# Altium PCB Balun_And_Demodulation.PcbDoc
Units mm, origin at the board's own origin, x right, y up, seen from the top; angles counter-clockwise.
Board outline 152.4 x 101.6 mm, 4 copper layers (Top Layer, GND, VCC, Bottom Layer), stack 1.593 mm thick; 57 components, 41 nets, 285 pads, 244 vias.
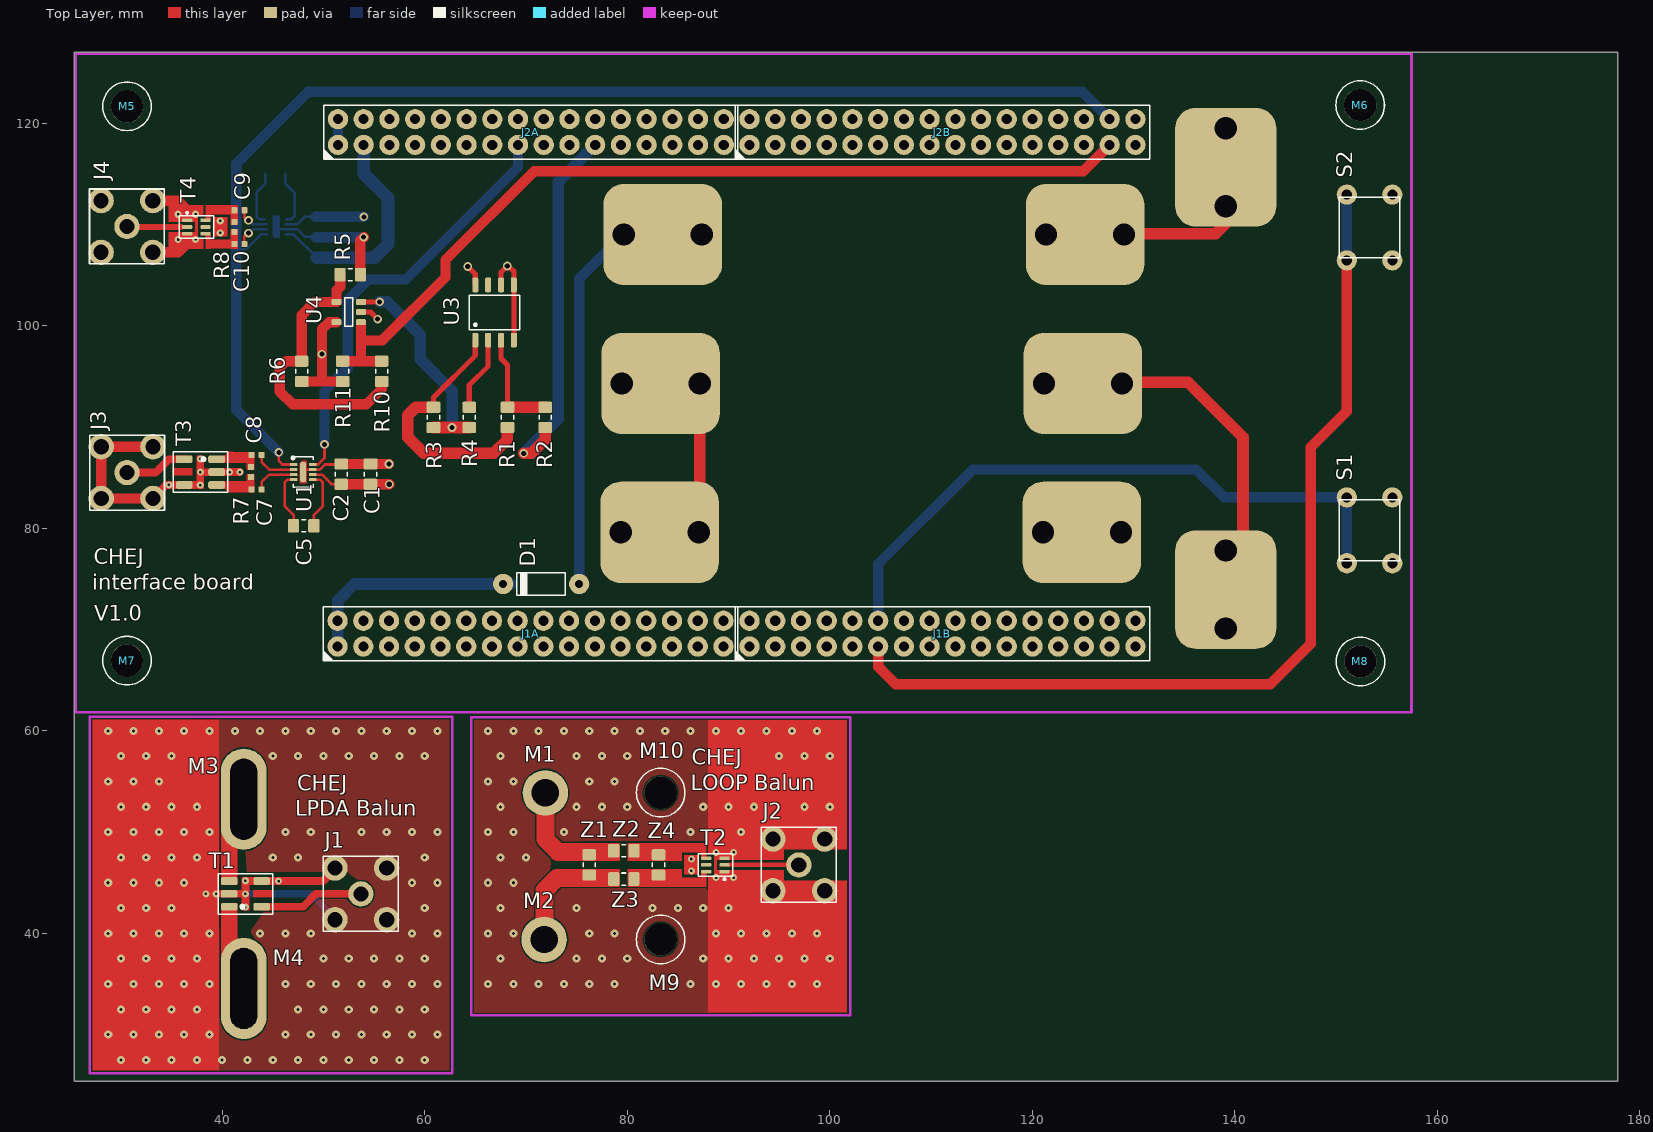
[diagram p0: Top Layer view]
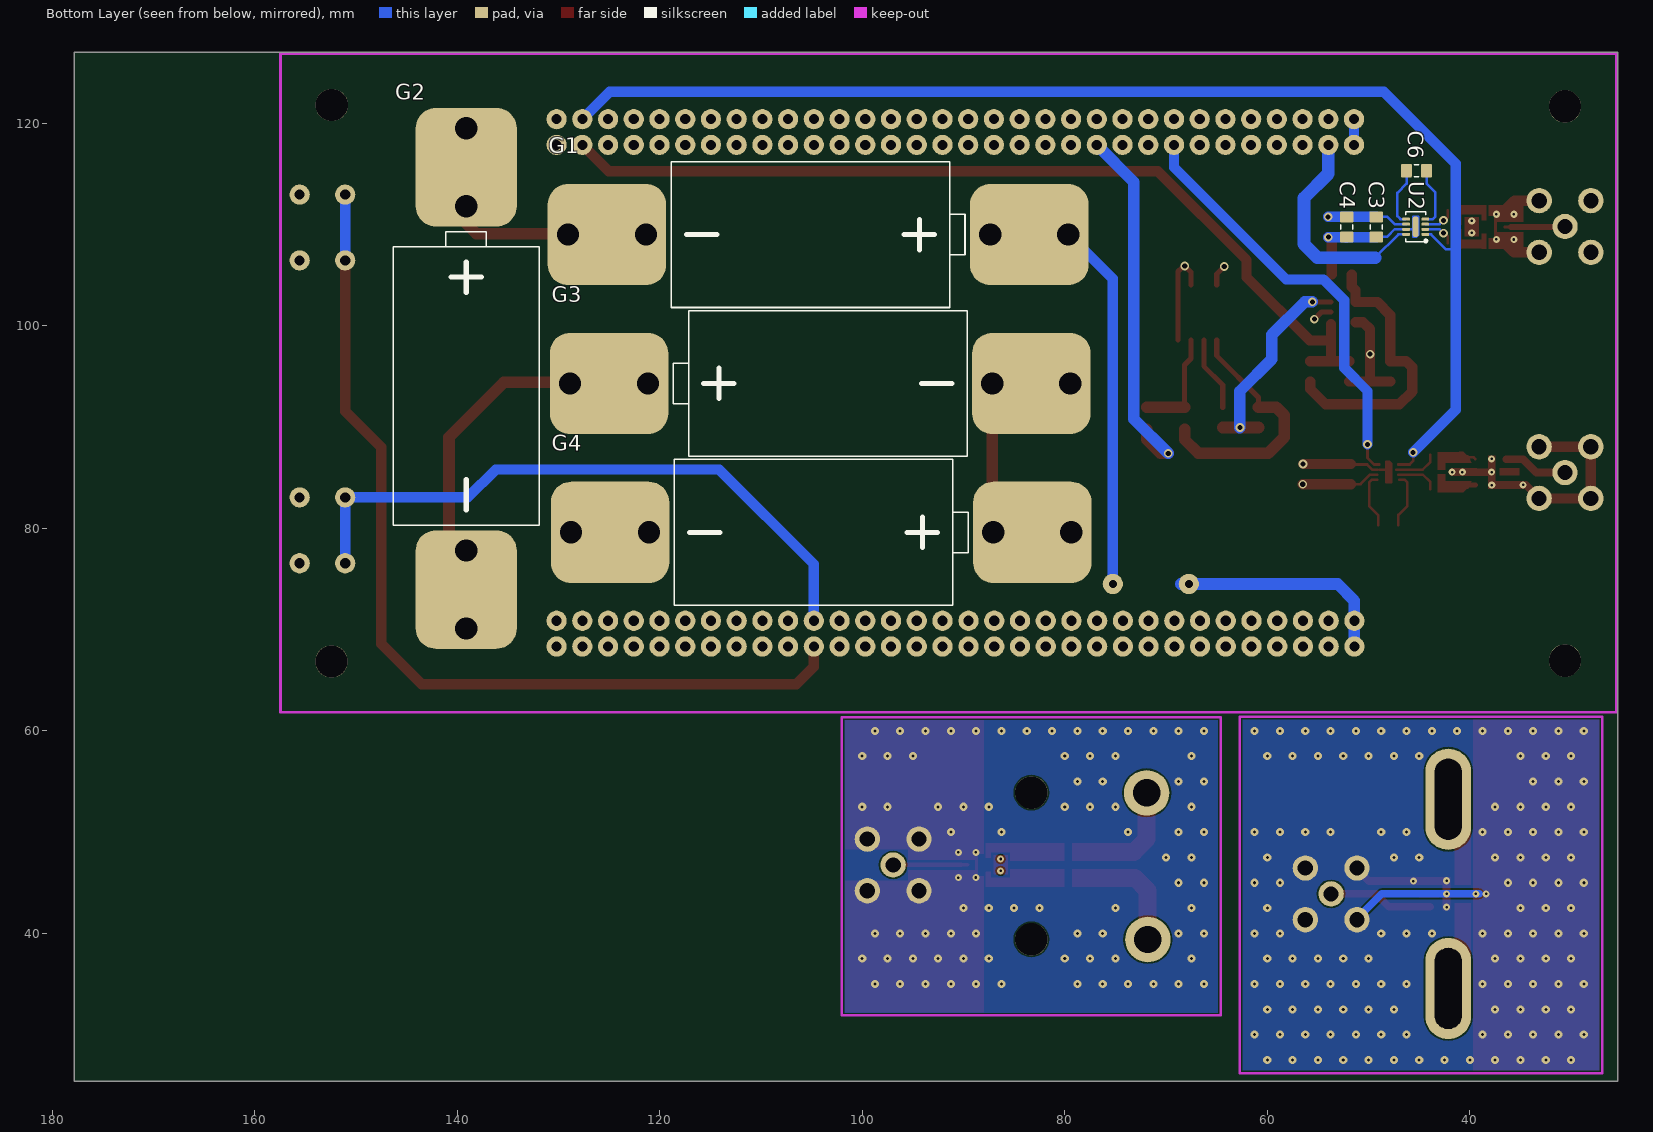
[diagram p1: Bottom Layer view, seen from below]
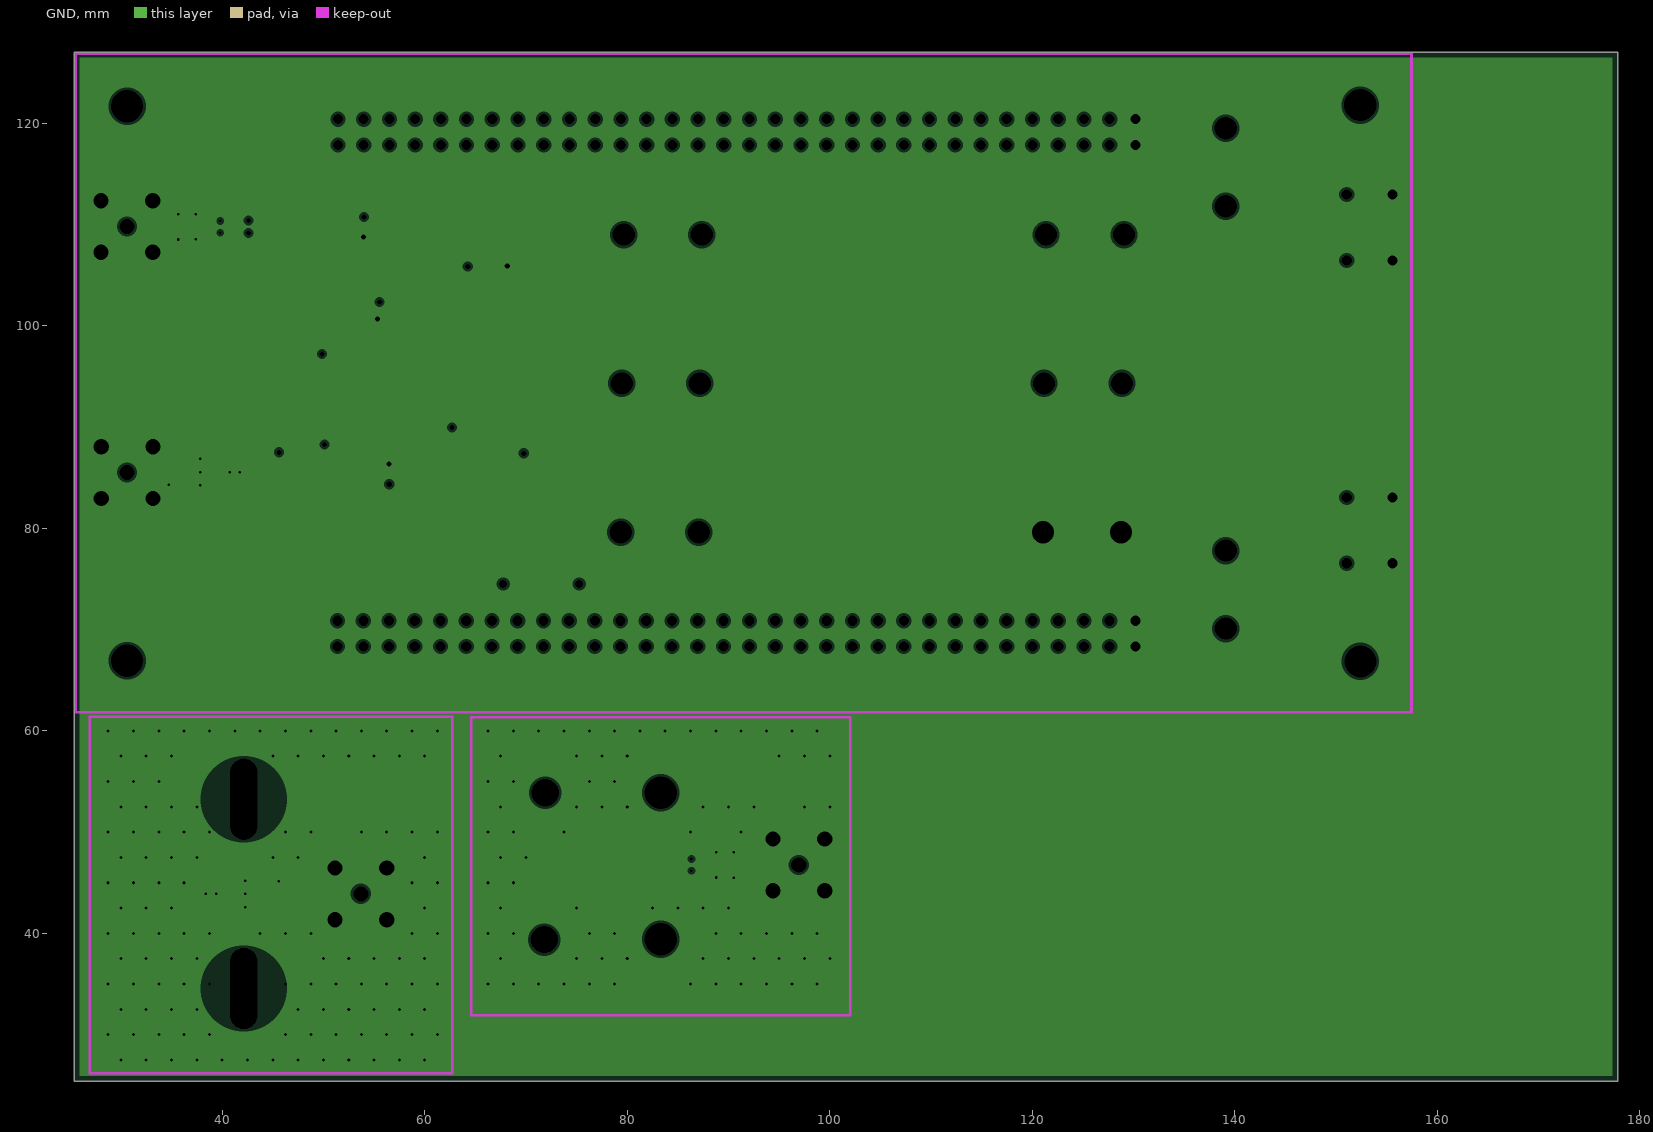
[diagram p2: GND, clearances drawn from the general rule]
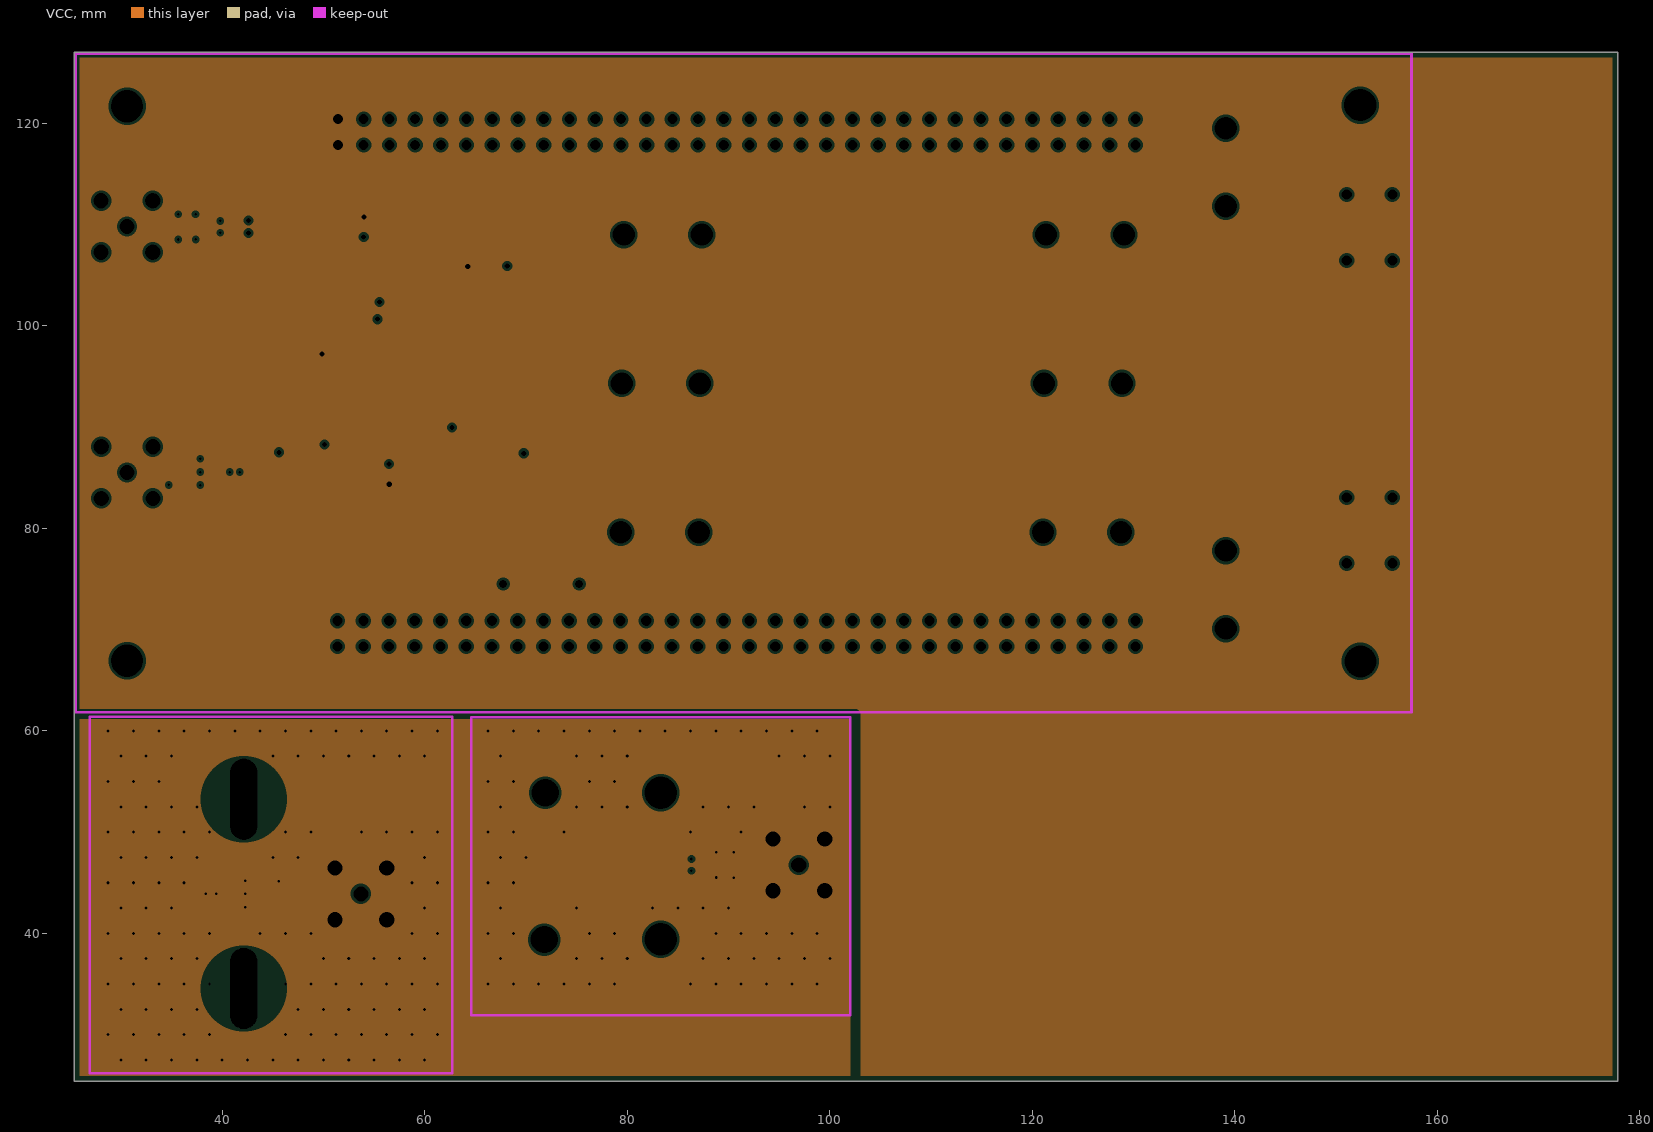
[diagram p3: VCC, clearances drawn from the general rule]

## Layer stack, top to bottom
Top Solder: solder mask 0.0102, Solder Resist, Dk 3.5
Top Layer: signal copper 0.0356
Dielectric 1: core 0.36, FR-4, Dk 4.2
GND: plane copper 0.036, net GND
Dielectric 5: prepreg 0.73, Dk 4.2
VCC: plane copper 0.036, net (Multiple Nets)
Dielectric 3: core 0.36, Dk 4.2
Bottom Layer: signal copper 0.0356
Bottom Solder: solder mask 0.0102, Solder Resist, Dk 3.5

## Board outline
25.4,25.4 177.8,25.4 177.8,127 25.4,127

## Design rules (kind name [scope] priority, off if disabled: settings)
BoardOutlineClearance [All] p1: gap=0.25 ignorepadtopadclearanceinfootprint=FALSE except(0: Arc-SplitContinuation Track-SplitContinuation SMDPad-SplitContinuation THPad-SplitContinuation Via-SplitContinuation Fill-SplitContinuation Poly-SplitContinuation Region-SplitContinuation Text-SplitContinuation)
Clearance Clearance-xPP-xTP-xTT [All] p1: gap=0.15 ignorepadtopadclearanceinfootprint=FALSE except(0: Arc-Hole Track-Hole SMDPad-Hole THPad-Hole Via-Hole Fill-Hole Poly-Hole Region-Hole Text-Hole)
ComponentClearance [All] p1: gap=0.25 collisioncheckmode=3 verticalgap=0.25 showdistances=FALSE
DiffPairsRouting [All] p1: maxlimit=0.25 minlimit=0.25 mostfreqgap=0.25 toplayer_minwidth=0.381 toplayer_maxwidth=0.381 toplayer_prefwidth=0.381 bottomlayer_minwidth=0.381 bottomlayer_maxwidth=0.381 bottomlayer_prefwidth=0.381 maxuncoupledlength=12.5
Height [All] p1: minheight=0 maxheight=25 prefheight=12.5
HoleSize HoleSize-PTH [All] p1: absolutevalues=TRUE maxlimit=2 minlimit=0.25 maxpercent=80.000 minpercent=20.000
HoleToHoleClearance [All] p1: gap=0.35 allowstackedmicrovias=TRUE
MinimumAnnularRing "Minimum IAR  >0.45mm" [((ObjectKind = 'Pad') OR (ObjectKind = 'Via')) And (Layer = 'MultiLayer') And (HoleDiameter > AsMM(0.45))] p1: minimumring=0.175 // minimum inner annular ring for pads > 0.45mm finished hole size
MinimumAnnularRing "Minimum IAR <=0.45mm" [((ObjectKind = 'Pad') OR (ObjectKind = 'Via')) And (Layer = 'MultiLayer') And (HoleDiameter <= AsMM(0.45))] p2: minimumring=0.175 // minimum inner annular ring for pads <= 0.45mm finished hole size
MinimumSolderMaskSliver [All] p1: minsoldermaskwidth=0.08
PlaneClearance PlaneClearance-IPI [All] p1: clearance=0.254
PlaneConnect [All] p1: planeconnectstyle=Direct reliefexpansion=0.175 reliefentries=4 reliefconductorwidth=0.2 reliefairgap=0.2
PolygonConnect PolygonConnect-xTW [All] p1: connectstyle=Direct reliefconductorwidth=0.2 reliefentries=4 polygonreliefangle="90 Angle" airgapwidth=0.2
RoutingCorners [All] p1: cornerstyle=45-Degree minsetback=2.5 maxsetback=2.5
RoutingVias "RoutingVias > 0.45mm" [(ObjectKind = 'Via') And (HoleDiameter > AsMM(0.45))] p1: holewidth=0.5 width=0.85 viastyle="Through Hole" minholewidth=0.5 minwidth=0.85 maxholewidth=0.9 maxwidth=1.25 // finishet hole size > 0.45mm
RoutingVias "RoutingVias <= 0.45mm" [(ObjectKind = 'Via') And (HoleDiameter <= AsMM(0.45))] p2: holewidth=0.3 width=0.65 viastyle="Through Hole" minholewidth=0.25 minwidth=0.6 maxholewidth=0.45 maxwidth=0.8 // finishet hole size <= 0.45mm
SilkToSilkClearance [All] p1: silktosilkclearance=0.2
SilkToSolderMaskClearance SilkscreenOverComponentPads [IsPad] p1: minsilkscreentomaskgap=0.2 clearancetoexposedcopper=TRUE
SolderMaskExpansion [All] p1: expansion=0
UnRoutedNet [All] p1: checkbadconnections=TRUE
Width Width-xTW [All] p1 off: maxlimit=1.5 minlimit=0.15 preferedwidth=0.2
18 further rules are at their usual default settings.

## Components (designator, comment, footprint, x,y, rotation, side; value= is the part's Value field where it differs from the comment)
C1 "1nF" "CAPACITOR 2012 REFLOW" 54.65,85.35 r270 top
C2 "100nF" "CAPACITOR 2012 REFLOW" 51.75,85.35 r270 top
C3 "100nF" "CAPACITOR 2012 REFLOW" 49.25,109.75 r90 bottom
C4 "1nF" "CAPACITOR 2012 REFLOW" 52.15,109.75 r90 bottom
C5 "*" "CAPACITOR 2012 REFLOW" 48.05,80.25 r180 top
C6 "*" "CAPACITOR 2012 REFLOW" 45.27,115.308 r180 bottom
C7 "=Value" "CAPACITOR 1005 REFLOW" 43.399,83.85 r180 top
C8 "=Value" "CAPACITOR 1005 REFLOW" 43.4,87.25 r180 top
C9 "=Value" "CAPACITOR 1005 REFLOW" 41.699,111.4 r180 top
C10 "=Value" "CAPACITOR 1005 REFLOW" 41.699,108.05 r180 top
D1 "*" "DIODE DO35 P7.5" 71.5,74.5 r0 top
G1 "1.5V" "1.5V Cell AA/LR6" 104.35,109 r0 bottom
G2 "1.5V" "1.5V Cell AA/LR6" 139.1,94.8 r270 bottom
G3 "1.5V" "1.5V Cell AA/LR6" 104.15,94.3 r180 bottom
G4 "1.5V" "1.5V Cell AA/LR6" 104.05,79.6 r0 bottom
J1 "CONSMA001-G" "SMA TH Vertical Linx CONSMA001-G" 53.696,43.9 r0 top
J1A "*" "PinHeader2x16 P2.54" 70.45,69.596 r0 top
J1B "*" "PinHeader2x16 P2.54" 111.125,69.596 r0 top
J2 "CONSMA001-G" "SMA TH Vertical Linx CONSMA001-G" 96.943,46.759 r0 top
J2A "*" "PinHeader2x16 P2.54" 70.485,119.126 r0 top
J2B "*" "PinHeader2x16 P2.54" 111.125,119.126 r0 top
J3 "CONSMA001-G" "SMA TH Vertical Linx CONSMA001-G" 30.607,85.5 r0 top
J4 "CONSMA001-G" "SMA TH Vertical Linx CONSMA001-G" 30.6,109.8 r0 top
M1 "=Value" "Screw Hex Socket M2.5X4 Connected"#1 71.915,53.871 r0 top
M2 "=Value" "Screw Hex Socket M2.5X4 Connected"#1 71.788,39.393 r0 top
M3 "=Value" "Screw Hex Socket M2.5X4 Connected"#2 42.134,53.244 r0 top
M4 "=Value" "Screw Hex Socket M2.5X4 Connected"#2 42.134,34.558 r0 top
M5 "*" "Screw M3X12 Unconnected" 30.607,121.666 r0 top
M6 "*" "Screw M3X12 Unconnected" 152.372,121.793 r0 top
M7 "*" "Screw M3X12 Unconnected" 30.607,66.929 r0 top
M8 "*" "Screw M3X12 Unconnected" 152.4,66.849 r0 top
M9 "*" "Screw M3X12 Unconnected" 83.3,39.4 r0 top
M10 "*" "Screw M3X12 Unconnected" 83.3,53.9 r0 top
R1 "*" "RESISTOR 2012 REFLOW" 68.17,90.95 r90 top
R2 "*" "RESISTOR 2012 REFLOW" 71.9,90.95 r270 top
R3 "0" "RESISTOR 2012 REFLOW" 60.865,90.95 r90 top
R4 "0" "RESISTOR 2012 REFLOW" 64.4,90.95 r90 top
R5 "*" "RESISTOR 2012 REFLOW" 52.65,105.05 r0 top
R6 "*" "RESISTOR 2012 REFLOW" 47.85,95.5 r90 top
R7 "0" "RESISTOR 1005 REFLOW" 42.85,85.55 r270 top
R8 "0" "RESISTOR 1005 REFLOW" 41.2,109.75 r90 top
R10 "*" "RESISTOR 2012 REFLOW" 55.75,95.5 r90 top
R11 "*" "RESISTOR 2012 REFLOW" 51.9,95.5 r270 top
S1 "*" "Push Button C6.0x6.0 WE 430186130716" 153.3,79.8 r90 top
S2 "*" "Push Button C6.0x6.0 WE 430186130716" 153.3,109.7 r90 top
T1 "{Value}" TC1-1TG2+ 42.3,43.9 r90 top
T2 "{Value}" NCS2-771-75+ 88.7,46.759 r90 top
T3 "{Value}" TC1-1TG2+ 37.85,85.55 r270 top
T4 "{Value}" NCS2-771-75+ 37.45,109.75 r270 top
U1 "ADM1085" "DFN8 P0.5 T0.6X1.2 C2.0X3.0 H0.8" 48,85.55 r0 top
U2 "ADM1085" "DFN8 P0.5 T0.6X1.2 C2.0X3.0 H0.8" 45.35,109.773 r0 bottom
U3 "*" "SO8 P1.27 C4.0X5.0 H1.75" 66.9,101.3 r90 top
U4 "LMV7239QDVB" "SOT23-5 P0.95 C1.6x3.0 H1.3" 52.5,101.35 r180 top
Z1 "*" "RESISTOR 2012 REFLOW" 76.233,46.759 r90 top
Z2 "*" "RESISTOR 2012 REFLOW" 79.662,48.156 r0 top
Z3 "*" "RESISTOR 2012 REFLOW" 79.662,45.362 r0 top
Z4 "*" "RESISTOR 2012 REFLOW" 83.091,46.759 r90 top

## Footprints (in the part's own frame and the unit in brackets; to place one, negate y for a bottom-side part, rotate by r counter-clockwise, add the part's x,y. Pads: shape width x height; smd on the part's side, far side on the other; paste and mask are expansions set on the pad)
"1.5V Cell AA/LR6" [mm] "Battery Cell D14.5 L50.5"
  rrect50% 8x10 hole 2.2 copper offset 2,0: 1(-24.7,0) 2(17,0)
  rrect50% 8x10 hole 2.2 copper offset -2,0: 1(-17,0) 2(24.7,0)
  silkscreen extent -14.5,-7.2 14.5,7.2, body extent -26.7,-7.2 26.8,7.2, height 15
"CAPACITOR 1005 REFLOW" [mm] "Capacitor SMD 1.0x0.5mm (0402-imperial)"
  rrect25% 0.6x0.6 smd: 1(-0.5,0) 2(0.499,0)
  body extent -0.5,-0.25 0.5,0.25, height 0.5
"CAPACITOR 2012 REFLOW" [mm] "Capacitor SMD 2.0x1.2mm (0805-imperial)"
  rrect25% 1.1x1.35 smd: 1(-1,0) 2(1,0)
  silkscreen extent -0.2,-0.6 0.2,0.6, body extent -1,-0.6 1,0.6, height 1
"DFN8 P0.5 T0.6X1.2 C2.0X3.0 H0.8" [mm] "DFN 8-Leads, Body 2.00x3.00mm, Pitch 0.5mm"
  rrect50% 0.75x0.3 smd: 1(-0.95,0.75) 2(-0.95,0.25) 3(-0.95,-0.25) 4(-0.95,-0.75) 5(0.95,-0.75) 6(0.95,-0.25) 7(0.95,0.25) 8(0.95,0.75)
  rrect75% 0.6x2 smd: 9(0,0)
  Top Layer region: 0.35,-1.05 0.35,1.05 0.3,1.1 -0.1,1.1 -0.35,0.85 -0.35,-1.05 -0.3,-1.1 0.3,-1.1
  silkscreen extent -1.1,-1.5 1,1.5, body extent -1,-1.5 1,1.5, height 0.81
"DIODE DO35 P7.5" [mm] "Diode DO35 pitch 7.5mm, Diameter 1.8mm, Case 4.3mm"
  round 2 hole 0.8: 1(-3.75,0) 2(3.75,0)
  silkscreen extent -2.4,-1.1 2.4,1.1, body extent -4.05,-0.91 4.05,0.91, height 1.82
NCS2-771-75+ [mm] "Mini-Circuits RF Transformer"
  rrect50% 0.36x1 smd: 1(-0.66,-0.9) 2(0,-0.9) 3(0.66,-0.9) 4(0.66,0.9) 5(0,0.9) 6(-0.66,0.9)
  silkscreen extent -1.5,-1.7 1.1,1.7, body extent -1,-0.6 1,0.6, height 0.94
"PinHeader2x16 P2.54" [mm] "Plug connector"
  round 2 hole 1: 1(-19.05,-1.27) 2(-19.05,1.27) 3(-16.51,-1.27) 4(-16.51,1.27) 5(-13.97,-1.27) 6(-13.97,1.27) 7(-11.43,-1.27) 8(-11.43,1.27) 9(-8.89,-1.27) 10(-8.89,1.27) 11(-6.35,-1.27) 12(-6.35,1.27) 13(-3.81,-1.27) 14(-3.81,1.27) 15(-1.27,-1.27) 16(-1.27,1.27) 17(1.27,-1.27) 18(1.27,1.27) 19(3.81,-1.27) 20(3.81,1.27) 21(6.35,-1.27) 22(6.35,1.27) 23(8.89,-1.27) 24(8.89,1.27) 25(11.43,-1.27) 26(11.43,1.27) 27(13.97,-1.27) 28(13.97,1.27) 29(16.51,-1.27) 30(16.51,1.27) 31(19.05,-1.27) 32(19.05,1.27)
  silkscreen extent -20.45,-2.67 20.45,2.67, body extent -20.32,-2.54 20.32,2.54, height 8.5
"Push Button C6.0x6.0 WE 430186130716" [mm] "Push Button Wurth Elektronik 430186130716"
  round 2 hole 1: 1(-3.25,2.25) 2(-3.25,-2.25) 3(3.25,2.25) 4(3.25,-2.25)
  silkscreen extent -3,-3 3,3, body extent -3.4,-3.1 3.4,3.1, height 15
"RESISTOR 1005 REFLOW" [mm] "Resistor SMD 1.0x0.5mm (0402-imperial)"
  rrect25% 0.6x0.6 smd: 1(-0.5,0) 2(0.5,0)
  body extent -0.5,-0.25 0.5,0.5, height 25
"RESISTOR 2012 REFLOW" [mm] "Resistor SMD 2.0x1.2mm (0805-imperial)"
  rrect25% 1.1x1.35 smd: 1(-1,0) 2(1,0)
  silkscreen extent -0.2,-0.6 0.2,0.6, body extent -1,-0.62 1,0.63, height 0.45
"Screw Hex Socket M2.5X4 Connected"#1 [mm] "Screw Hex Socket M2.5X4 Connected BN610"
  round 4.5 hole 2.7 paste-5 mask+0: 1(0,0)
  body extent -2.25,-2.25 2.25,2.25, height 2.5
"Screw Hex Socket M2.5X4 Connected"#2 [mm] "Screw Hex Socket M2.5X4 Connected BN610"
  oval 4.5x10 hole 2.7 slot 8 at 90 deg paste-5 mask+0: 1(0,0)
  body extent -2.25,-2.25 2.25,2.25, height 2.5
"Screw M3X12 Unconnected" [mm] "Standard Screw M3X12 Unconnected BN330"
  round 3.2 hole 3.2 unplated paste+0 mask+0: 0(0,0)
  silkscreen extent -2.4,-2.4 2.4,2.4, body extent -2.29,-2.3 2.29,2.3, height 2
"SMA TH Vertical Linx CONSMA001-G" [mm] "Connector SMA Trough Hole Vertical Linx nr. CONSMA001-G"
  round 2.5 hole 1.5: 1(0,0) 2(-2.55,-2.55) 2(-2.55,2.55) 2(2.55,-2.55) 2(2.55,2.55)
  silkscreen extent -3.7,-3.7 3.7,3.7, body extent -3.5,-3.5 3.5,3.5, height 10.25
"SO8 P1.27 C4.0X5.0 H1.75" [mm] "8-Pin Small Outline Integrated Circuit 1.27 mm Pitch, IPC Medium Density"
  rrect50% 1.45x0.6 smd: 1(-2.725,1.905) 2(-2.725,0.635) 3(-2.725,-0.635) 4(-2.725,-1.905) 5(2.725,-1.905) 6(2.725,-0.635) 7(2.725,0.635) 8(2.725,1.905)
  silkscreen extent -1.7,-2.5 1.7,2.5, body extent -2,-2.5 2,2.5, height 1.76
"SOT23-5 P0.95 C1.6x3.0 H1.3" [mm] "SOT23, 5-Leads, Body 1.6x3.0mm, Pitch 0.95mm, IPC Medium Density"
  rrect50% 1x0.6 smd: 1(-1.2,1) 2(-1.2,0) 3(-1.2,-1) 4(1.2,-1) 5(1.2,1)
  silkscreen extent -0.4,-1.4 0.4,1.4, body extent -0.8,-1.5 0.8,1.5, height 1.3
TC1-1TG2+ [mm] "Mini-Circuits RF Transformer"
  rrect50% 0.76x1.65 smd: 1(-1.27,1.6) 2(0,1.6) 3(1.27,1.6) 4(1.27,-1.6) 6(-1.27,-1.6)
  silkscreen extent -2,-2.7 2,2.7, body extent -1.9,-1.9 1.9,1.9, height 3.81

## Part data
C1 C2 C3 C4 C5 C6 C7 C8 C9 C10: library part Capacitor, "Capacitor"
D1: library part DIODE, "Diode generic 2 leads"
G1 G2 G3 G4: library part Battery, "Battery Generic"
J1 J2 J3 J4: library part "SMA TH VERTICAL LINX CONSMA001-G", "SMA TH VERTICAL LINX CONSMA001-G"
J1A J1B J2A J2B: library part PinHeader2x16, "Plug connector"
M1 M2 M3 M4: library part "Screw Hex Socket Connected", "Screw Hex Socket Connected BN610"
M5 M6 M7 M8 M9 M10: library part "Screw Unconnected", "Screw Unconnected BN330"
R1 R2 R3 R4 R5 R6 R7 R8 R10 R11 Z1 Z2 Z3 Z4: library part Resistor, "Resistor"
S1 S2: library part "Push Button 4Pins", "Push Button, 4 pins, 2 poles parrallèle"
T1 T3: library part TC1-1TG2+, "Mini-Circuits RF Transformer"
T2 T4: library part NCS2-771-75+, "Mini-Circuits RF Transformer"
U1 U2: library part LT5537, "Wide Dynamic Range RF/IF Log Detector"
U3: library part "OPA DUAL", "Generic dual OPA 8 pins"
U4: library part "COMPARATOR SINGLE SOT23-5", "Generic Single Comparator 5pins 1OUT/2-V/3+IN/4-IN/5+V"

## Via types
v1: diameter 0.8, hole 0.3, Top Layer to Bottom Layer, 205 vias
v2: diameter 0.7, hole 0.25, Top Layer to Bottom Layer, 24 vias
v3: diameter 0.85, hole 0.5, Top Layer to Bottom Layer, 15 vias

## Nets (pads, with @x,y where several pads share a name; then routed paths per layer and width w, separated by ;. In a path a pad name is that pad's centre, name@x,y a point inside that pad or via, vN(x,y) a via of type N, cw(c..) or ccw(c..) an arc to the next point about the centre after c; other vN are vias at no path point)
+3: C1.2 C2.2 C3.2 C4.2 J2A.1 J2A.2 R6.1 R11.2 U1.6 U2.6 U3.8 U4.5 | length 31.4
  Top Layer w0.254: U1.6@49.15,85.3 49.85,85.3 50.8,84.35 C2.2
  Top Layer w0.508: v3(64.25,105.85) 64.995,105.105 U3.8
  Top Layer w1.016: R6.1 49.85,94.5 ; U4.5 50.55,100.35 49.85,99.65 v3(49.85,97.2) 49.85,94.5 ; C2.2 C1.2 v3(56.5,84.35) ; R11.2 49.85,94.5
  Bottom Layer w0.254: U2.6 47.423,110.023 48.15,110.75 C3.2
  Bottom Layer w1.016: C3.2 52.15,110.75 v3(54,110.75) ; J2A.1 J2A.2
+5: D1.1 J1A.1 J1A.2 | length 22.4
  Bottom Layer w1.143: J1A.1 J1A.2 51.4,72.85 53.05,74.5 D1.1@68.55,74.5
GND: C1.1 C2.1 C3.1 C4.1 G4.2 J1.2 J1B.31 J1B.32 J2.2 J2B.31 J2B.32 J3.2 J4.2 R5.2 S1.2 S1.4 S2.2 S2.4 T1.2 T1.4 T2.1 T2.3 T3.2 T3.4 T4.1 T4.3 U1.7 U1.9 U2.7 U2.9 U3.4 U3.5 U3.6 U4.2 | length 96.9
  Top Layer w0.254: U1.9 48.25,85.8 U1.7 ; U1.7@49.15,85.8 49.65,85.8 50.15,86.3 51.7,86.3 C2.1
  Top Layer w0.508: U4.2 54.65,101.35 v3(55.35,100.65) ; U3.6 67.535,105.285 v3(68.15,105.9) ; v3@68.15,105.75 68.4,105.75 68.805,105.345 U3.5 U3.4
  Top Layer w0.762: J3.2@33.157,82.95 34.486,84.279 v2(34.737,84.279) v2(34.737,84.279) T3.4 37.845,84.28 37.845,85.54 39.445,85.55 T3.2 v2(40.745,85.55) v2(41.745,85.55) ; v2(38.4,43.9) v2(39.4,43.9) T1.2 42.29,43.9 42.3,43.91 42.3,45.18 42.31,45.17 T1.4 v2(45.57,45.17) 49.97,45.17 J1.2@51.25,46.45
  Top Layer w1.016: J4.2@33.15,107.25 35.65,107.25 36.3,107.9 ; J4.2@33.15,112.35 35.6,112.35 36.55,111.4 ; J3.2@33.157,82.95 28.057,82.95 28.057,88.05 J3.2@33.157,88.05 ; C2.1 C1.1 v3(56.48,86.35) ; R5.2 53.65,108.425 v3(53.975,108.75)
  Top Layer w1.143: G4.2@128.225,79.075 128.75,79.6 G4.2@130.175,78.175
  Bottom Layer w0.254: U2.9 45.6,109.523 U2.7 ; U2.7@46.3,109.527 47.423,109.527 48.15,108.8 C3.1@49.25,108.8
  Bottom Layer w0.762: v2@39.1,43.9 v2(39.4,43.9) v2(42.3,43.9) 48.7,43.9 J1.2@51.25,41.35
  Bottom Layer w1.016: C3.1 C4.1@52.15,108.75 ; C4.1@52.2,108.7 C4.1 ; v3(53.975,108.75) C4.1
  Bottom Layer w1.143: J2B.32 J2B.32@130.335,120.396
  other v1: 30,27.5 32.5,27.5 35,27.5 37.5,27.5 40,27.5 42.5,27.5 45,27.5 47.5,27.5 50,27.5 52.5,27.5 55,27.5 57.5,27.5 60,27.5 28.75,30 31.25,30 33.75,30 36.25,30 38.75,30 46.25,30 48.75,30 51.25,30 53.75,30 56.25,30 58.75,30 61.25,30 30,32.5 32.5,32.5 35,32.5 37.5,32.5 47.5,32.5 50,32.5 52.5,32.5 55,32.5 57.5,32.5 60,32.5 28.75,35 31.25,35 33.75,35 36.25,35 38.75,35 46.25,35 48.75,35 51.25,35 53.75,35 56.25,35 58.75,35 61.25,35 66.25,35 68.75,35 71.25,35 73.75,35 76.25,35 78.75,35 86.25,35 88.75,35 91.25,35 93.75,35 96.25,35 98.75,35 30,37.5 32.5,37.5 35,37.5 37.5,37.5 50,37.5 52.5,37.5 55,37.5 57.5,37.5 60,37.5 67.5,37.5 75,37.5 77.5,37.5 80,37.5 87.5,37.5 90,37.5 92.5,37.5 95,37.5 97.5,37.5 100,37.5 28.75,40 31.25,40 33.75,40 36.25,40 38.75,40 43.75,40 46.25,40 48.75,40 58.75,40 61.25,40 66.25,40 68.75,40 76.25,40 78.75,40 88.75,40 91.25,40 93.75,40 96.25,40 98.75,40 30,42.5 32.5,42.5 35,42.5 60,42.5 67.5,42.5 75,42.5 82.5,42.5 85,42.5 87.5,42.5 90,42.5 28.75,45 31.25,45 33.75,45 36.25,45 58.75,45 61.25,45 66.25,45 68.75,45 30,47.5 32.5,47.5 35,47.5 37.5,47.5 45,47.5 47.5,47.5 60,47.5 67.5,47.5 70,47.5 28.75,50 31.25,50 33.75,50 36.25,50 38.75,50 46.25,50 48.75,50 53.75,50 56.25,50 58.75,50 61.25,50 66.25,50 68.75,50 73.75,50 86.25,50 91.25,50 30,52.5 32.5,52.5 35,52.5 37.5,52.5 67.5,52.5 75,52.5 77.5,52.5 80,52.5 87.5,52.5 90,52.5 92.5,52.5 97.5,52.5 100,52.5 28.75,55 31.25,55 33.75,55 66.25,55 68.75,55 76.25,55 78.75,55 30,57.5 32.5,57.5 35,57.5 45,57.5 47.5,57.5 50,57.5 52.5,57.5 55,57.5 57.5,57.5 60,57.5 67.5,57.5 75,57.5 77.5,57.5 80,57.5 95,57.5 97.5,57.5 100,57.5 28.75,60 31.25,60 33.75,60 36.25,60 38.75,60 41.25,60 43.75,60 46.25,60 48.75,60 51.25,60 53.75,60 56.25,60 58.75,60 61.25,60 66.25,60 68.75,60 71.25,60 73.75,60 76.25,60 78.75,60 81.25,60 83.75,60 86.25,60 88.75,60 91.25,60 93.75,60 96.25,60 98.75,60
  other v2: 42.3,42.6 42.3,45.2 88.773,45.517 90.5,45.515 88.776,48.004 90.5,48.004 37.838,84.27 37.845,85.55 37.845,86.85 35.65,108.515 37.377,108.517 35.65,111.004 37.374,111.004
NetC5_1: C5.1 U1.5 | length 5.5
  Top Layer w0.254: C5.1@49.05,80.3 49.05,81.3 49.95,82.2 49.95,84.5 49.65,84.8 U1.5@49.15,84.8
NetC5_2: C5.2 U1.4 | length 5.5
  Top Layer w0.254: U1.4@46.96,84.8 46.46,84.8 46.16,84.5 46.16,82.2 47.05,81.31 C5.2@47.05,80.3
NetC6_1: C6.1 U2.5 | length 5.5
  Bottom Layer w0.254: C6.1@46.25,115.023 46.25,114.023 47.15,113.123 47.15,110.823 46.85,110.523 U2.5@46.35,110.523
NetC6_2: C6.2 U2.4 | length 5.5
  Bottom Layer w0.254: U2.4@44.16,110.523 43.66,110.523 43.4,110.783 43.4,113.163 44.25,114.013 C6.2@44.25,115.023
NetC7_1: C7.1 U1.3 | length 4.2
  Top Layer w0.254: C7.1 43.899,84.549 44.65,85.3 U1.3
NetC7_2: C7.2 R7.2 T3.3 | length 3.3
  Top Layer w0.508: T3.3 42.19,84.28 42.36,84.11
  Top Layer w1.1: 42.36,84.11 C7.2@42.65,84.11
NetC8_1: C8.1 U1.2 | length 4.4
  Top Layer w0.254: C8.1 43.9,86.55 44.65,85.8 U1.2@47.25,85.8
NetC8_2: C8.2 R7.1 T3.1 | length 3.2
  Top Layer w0.254: T3.1 39.63,87 42.31,87
  Top Layer w1.1: 42.31,87 42.6,87
NetC9_1: C9.1 U2.3 | length 3.2
  Top Layer w0.254: C9.1 42.199,110.701 42.5,110.4 v3(42.6,110.4)
  Bottom Layer w0.254: v3@42.6,110.357 v3(42.6,110.4) 42.977,110.023 U2.3
NetC9_2: C9.2 R8.2 T4.6
NetC10_1: C10.1 U2.2 | length 3.1
  Top Layer w0.254: C10.1@42.199,108.15 42.199,108.849 v3@42.5,109.15
  Bottom Layer w0.254: v3(42.6,109.15) 42.977,109.527 U2.2@44.4,109.527
NetC10_2: C10.2 R8.1 T4.4
NetD1_2: D1.2 G1.1 | length 36.4
  Bottom Layer w1.016: D1.2 75.25,104.65 79.6,109 G1.1@79.65,109
NetG1_2: G1.2 G2.1 | length 10.9
  Top Layer w1.143: G1.2@131,109.1 138.1,109.1 G2.1@140.8,111.8
NetG2_2: G2.2 G3.1 | length 23.4
  Top Layer w1.143: G3.1@130.8,94.4 135.4,94.4 140.8,89 G2.2@140.8,77.8
NetG3_2: G3.2 G4.1 | length 14.7
  Top Layer w1.143: G4.1@87.05,79.6 87.15,79.7 G3.2@87.15,94.3
NetJ1_1: J1.1 T1.6 | length 10.4
  Top Layer w0.762: T1.6 48,42.63 49.27,43.9 J1.1@53.8,43.9
NetJ1B_11: J1B.11 S2.1 S2.3 | length 92.9
  Top Layer w1.016: J1B.11 104.775,66.325 106.508,64.592 143.492,64.592 147.5,68.6 147.5,88 151.05,91.55 S2.1
  Bottom Layer w1.016: S2.1 S2.3
NetJ1B_12: J1B.12 S1.1 S1.3 | length 62.4
  Bottom Layer w1.016: J1B.12 104.775,76.475 114.1,85.8 136.2,85.8 138.95,83.05 S1.3@150.05,83.05 ; S1.1 S1.3
NetJ2_1: J2.1 T2.2 | length 7.3
  Top Layer w0.36: T2.2 90.2,46.759
  Top Layer w0.457: 90.2,46.759 J2.1
NetJ2A_3: J2A.3 U2.8 | length 22.4
  Bottom Layer w0.254: U2.8 47.06,109.023 49.365,106.718
  Bottom Layer w1.27: 49.365,106.718 55.035,106.718 56.37,108.053 56.37,112.624 53.975,115.019 J2A.3
NetJ2A_15: J2A.15 U1.8 | length 42.4
  Top Layer w0.254: U1.8 49.46,86.3 50.106,86.946 v3(50.106,88.28)
  Bottom Layer w1.016: v3(50.106,88.28) 50.106,93.552 52.411,95.857 52.411,102.517 54.465,104.571 58.157,104.571 69.215,115.629 J2A.15
NetJ2A_21: J2A.21 R2.2 | length 37.1
  Top Layer w1.143: v3(69.781,87.4) 70.542,87.4 71.912,88.77 R2.2@71.912,89.777
  Bottom Layer w1.143: v3(69.781,87.4) 73.175,90.794 73.175,114.196 J2A.21
NetJ2B_29: J2B.29 R10.2 R11.1 U4.1 | length 90.4
  Top Layer w1.016: R11.1 53.7,96.5 ; U4.1@53.7,100.15 53.7,98.55 ; R10.2 53.7,96.5 ; J2B.29 125.029,115.25 70.8,115.25 62.05,106.5 62.05,104.8 55.8,98.55 53.7,98.55 ; 53.7,96.5 53.7,98.55
NetJ2B_30: J2B.30 U1.1 U2.1 | length 126.6
  Top Layer w0.254: v3(45.6,87.5) 45.6,86.65 45.95,86.3 U1.1
  Bottom Layer w0.254: 41.4,107.55 42.35,107.55 43.823,109.023 U2.1
  Bottom Layer w1.016: v3(45.6,87.5) 41.4,91.7 41.4,107.55 41.4,116 48.5,123.1 124.931,123.1 J2B.30
NetJ3_1: J3.1 T3.6 | length 6.3
  Top Layer w0.762: J3.1 33.42,85.5 34.75,86.83 T3.6@36.4,86.83
NetJ4_1: J4.1 T4.2 | length 6
  Top Layer w0.254: 35.95,109.759 35.959,109.75 T4.2
  Top Layer w0.457: J4.1 J4.1@30.641,109.759
  Top Layer w0.611: J4.1@30.641,109.759 35.95,109.759
NetM1_1: M1.1 Z1.2 Z2.1 | length 9
  Top Layer w0.254: Z1.2@75.963,48.029 Z1.2
  Top Layer w1.778: M1.1 71.915,49.296 73.182,48.029 75.471,48.029
NetM2_1: M2.1 Z1.1 Z3.1 | length 9.7
  Top Layer w1.778: M2.1@71.815,39.647 71.815,44.222 73.082,45.489 Z1.1@76.383,45.489
NetM3_1: M3.1 T1.3 | length 5.8
  Top Layer w1.1: 40.671,48.315 40.671,51.224 M3.1@42.713,53.266 ; M3.1@41.885,50.7 M3.1@41.905,50.7
NetM4_1: M4.1 T1.1 | length 5.3
  Top Layer w1.1: 40.787,39.199 40.787,35.905 M4.1 ; M4.1@41.841,37.059 M4.1@41.9,37
NetR1_1: R1.1 R3.2 U3.1 | length 25.5
  Top Layer w0.508: R3.2 60.865,92.915 64.995,97.045 U3.1
  Top Layer w1.143: R3.2 59.1,91.95 58.325,91.175 58.325,88.975 59.9,87.4 66.8,87.4 68.17,88.77 R1.1@68.17,89.777
NetR1_2: R1.2 R2.1 U3.3 | length 10.6
  Top Layer w0.508: U3.3 67.535,96.765 68.17,96.13 R1.2
  Top Layer w1.143: R1.2 R2.1
NetR3_1: R3.1 R4.1 U4.3 | length 21.2
  Top Layer w0.508: U4.3 v3(55.55,102.35)
  Top Layer w1.143: R3.1 v3(62.7,89.95) R4.1
  Bottom Layer w1.143: v3(55.55,102.35) 56.315,102.35 59.55,99.115 59.55,96.7 62.7,93.55 v3(62.7,89.95)
NetR4_2: R4.2 U3.2 | length 7.4
  Top Layer w0.508: R4.2 64.4,94.145 66.265,96.01 U3.2
NetR5_1: R5.1 R6.2 R10.1 U4.4 | length 28.1
  Top Layer w1.016: R5.1 51.65,103.85 51.3,103.5 U4.4 49.15,102.35 47.85,101.05 R6.2 46.3,96.5 45.7,95.9 45.7,93.5 46.95,92.25 54.25,92.25 55.75,93.75 R10.1
NetT2_4: T2.4 Z2.2 Z4.2 | length 0.4
  Top Layer w0.254: Z4.2 Z4.2@83.361,48.029
NetT2_6: T2.6 Z3.2 Z4.1
pads on no net: J1A.3 J1A.4 J1A.5 J1A.6 J1A.7 J1A.8 J1A.9 J1A.10 J1A.11 J1A.12 J1A.13 J1A.14 J1A.15 J1A.16 J1A.17 J1A.18 J1A.19 J1A.20 J1A.21 J1A.22 J1A.23 J1A.24 J1A.25 J1A.26 J1A.27 J1A.28 J1A.29 J1A.30 J1A.31 J1A.32 J1B.1 J1B.2 J1B.3 J1B.4 J1B.5 J1B.6 J1B.7 J1B.8 J1B.9 J1B.10 J1B.13 J1B.14 J1B.15 J1B.16 J1B.17 J1B.18 J1B.19 J1B.20 J1B.21 J1B.22 J1B.23 J1B.24 J1B.25 J1B.26 J1B.27 J1B.28 J1B.29 J1B.30 J2A.4 J2A.5 J2A.6 J2A.7 J2A.8 J2A.9 J2A.10 J2A.11 J2A.12 J2A.13 J2A.14 J2A.16 J2A.17 J2A.18 J2A.19 J2A.20 J2A.22 J2A.23 J2A.24 J2A.25 J2A.26 J2A.27 J2A.28 J2A.29 J2A.30 J2A.31 J2A.32 J2B.1 J2B.2 J2B.3 J2B.4 J2B.5 J2B.6 J2B.7 J2B.8 J2B.9 J2B.10 J2B.11 J2B.12 J2B.13 J2B.14 J2B.15 J2B.16 J2B.17 J2B.18 J2B.19 J2B.20 J2B.21 J2B.22 J2B.23 J2B.24 J2B.25 J2B.26 J2B.27 J2B.28 M5.0 M6.0 M7.0 M8.0 M9.0 M10.0 T2.5 T4.5 U3.7
copper on no net:
  other v2: 86.338,46.176 86.338,47.344 39.812,109.176 39.812,110.344

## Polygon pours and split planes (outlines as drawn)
GND on Top Layer "Top Layer-NetJ1_2" (solid, pour order 40): 26.927,61.4 26.927,26.2 62.45,26.2 62.45,61.4
GND on Top Layer "Top Layer-NetJ2_2" (solid, pour order 30): 64.599,61.334 64.599,31.9 64.649,31.95 92.35,31.95 92.35,61.353 88.25,61.35
no net on Top Layer "Top Layer-No Net 1" (solid, pour order 20): 40.008,42.261
no net on Top Layer "Top Layer-No Net 2" (solid, pour order 18): 40.008,45.539
no net on Top Layer "Top Layer-No Net 3" (solid, pour order 16): 88.062,48.514
no net on Top Layer "Top Layer-No Net 4" (solid, pour order 12): 89.129,47.269
no net on Top Layer "Top Layer-No Net 5" (solid, pour order 10): 77.884,46.632
no net on Top Layer "Top Layer-No Net 6" (solid, pour order 4): 75.598,46.378
GND on Bottom Layer "Bottom Layer-NetJ1_2" (solid, pour order 38): 26.927,61.4 26.927,26.2 62.4,26.2 62.4,61.4
GND on Bottom Layer "Bottom Layer-NetJ2_2" (solid, pour order 34): 64.599,61.334 64.599,31.9 102.023,31.9 102.023,61.334
GND on GND (split plane): 177.29,25.91 25.91,25.91 25.91,126.49 177.29,126.49
GND on VCC (split plane): 102.032,25.91 25.91,25.91 25.91,61.15 102.032,61.15
+3 on VCC (split plane): 177.29,25.91 103.036,25.91 103.036,61.652 103.027,61.75 102.998,61.844 102.952,61.931 102.889,62.007 102.813,62.07 102.726,62.116 102.632,62.145 102.534,62.154 25.91,62.154 25.91,126.49 177.29,126.49

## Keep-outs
Keep-Out Layer:
  lines w0.254: 102.023,61.294 102.023,31.9 64.599,31.9 64.599,45.459 64.599,61.334 102.023,61.334 ; 157.372,126.873 25.527,126.873 25.527,61.849 157.441,61.849 157.441,126.873 ; 26.927,26.2 62.7,26.2 62.7,56.434 62.7,61.4 26.927,61.4 26.927,46.943 26.927,39.45 26.927,32.084 26.927,26.2

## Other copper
Top Layer:
  rectangle net GND: 27.209,26.48 39.689,61.123
  rectangle net NetM4_1: 39.87,36.565 41.526,43.019
  rectangle net NetM3_1: 39.874,44.791 41.525,50.646
  rectangle net NetC7_2: 42.4,83.55 43.2,85.35
  rectangle net NetC8_2: 42.4,85.75 43.2,87.55
  region net NetC7_2: 42.65,84.65 40.75,84.65 40.75,83.55 42.65,83.55
  region net NetC8_2: 42.65,87.55 40.75,87.55 40.75,86.45 42.65,86.45
  rectangle: 35.12,85.19 37.07,85.93
  rectangle net GND: 37.46,83.9 38.23,87.21
  rectangle net NetC10_2: 40.8,107.6 41.55,109.568
  rectangle net NetC9_2: 40.8,109.95 41.55,111.918
  region net NetC10_2: 38.85,109.1 38.342,109.1 38.342,107.6 38.85,107.6
  region net NetC9_2: 38.85,111.918 38.342,111.918 38.342,110.373 38.85,110.373
  region net GND: 37.606,110.6 37.301,110.6 37.301,108.923 37.606,108.923
  region net GND: 37.606,110.879 34.7,110.879 34.7,110.223 37.606,110.223
  region net GND: 37.606,109.279 34.7,109.279 34.7,108.644 37.606,108.644
  region net GND: 38.18,111.918 34.7,111.918 34.7,110.854 38.18,110.854
  region net GND: 38.18,108.669 34.7,108.669 34.7,107.6 38.18,107.6
  region: 40.527,110.727 39.104,110.727 39.104,108.822 40.527,108.822
  region net NetC9_2: 41.55,111.918 38.449,111.918 38.449,111.006 41.55,111.006
  region net NetC10_2: 41.55,108.514 38.373,108.514 38.373,107.602 41.55,107.602
  rectangle net NetT2_6: 83.414,45.441 85.395,46.378
  rectangle net NetT2_4: 83.642,47.142 85.395,48.285
  rectangle net NetT2_6: 83.795,44.602 87.427,45.514
  rectangle net NetT2_4: 83.718,48.006 87.351,48.918
  rectangle: 43.07,43.54 45.02,44.28
  rectangle net GND: 41.91,42.25 42.68,45.56
  rectangle net GND: 87.964,48.3 101.7,61.052
  rectangle net GND: 87.964,32.182 101.7,45.2
  rectangle: 85.623,45.822 87.046,47.727
  rectangle net GND: 87.97,44.4 95.5,45.669
  rectangle net GND: 87.97,47.854 95.5,48.918
  rectangle net GND: 88.544,45.644 95.5,46.279
  rectangle net GND: 88.544,47.244 95.5,47.879
  rectangle net GND: 88.544,45.923 88.849,47.6
  rectangle net NetT2_4: 87.3,47.419 87.808,48.918
  rectangle net NetT2_6: 87.3,44.6 87.808,46.1
  rectangle net NetT2_6: 80.043,44.6 83.853,46.378
  rectangle net NetT2_4: 80.043,47.14 83.853,48.918
  rectangle net NetM1_1: 75.471,47.14 79.281,48.918
  rectangle net NetM2_1: 75.471,44.6 79.281,46.378
  region net NetC7_2: 40.142,83.911 40.289,83.911 40.65,83.55 41.05,83.55 41.05,84.35 40.75,84.65 39.85,84.65
  region net NetC8_2: 40.142,87.189 40.289,87.189 40.65,87.55 41.05,87.55 41.05,86.75 40.75,86.45 39.85,86.45
  region net NetM4_1: 40.008,42.261
  region: 40,41.9
  region: 40,45.9
  region: 40.008,45.539
VCC (plane layer: these items are gaps in the copper):
  lines w1: 25.403,61.652 102.534,61.652 102.534,25.355

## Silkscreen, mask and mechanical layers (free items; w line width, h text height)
Top Overlay:
  text "CHEJ" at 27.3,76.45 h1.52
  text "interface board" at 27.15,73.95 h1.52
  text "V1.0" at 27.35,70.866 h1.52
  text "CHEJ" at 86.35,56.654 h1.52
  text "LOOP Balun" at 86.283,54.156 h1.52
  text "CHEJ" at 47.4,54.1 h1.52
  text "LPDA Balun" at 47.2,51.6 h1.52
Mechanical 1:
  lines w0.254: 25.527,66.929 30.607,66.929 30.607,61.849 ; 25.527,121.666 30.607,121.666 30.607,126.746 ; 26.927,43.9 32,43.9 62.7,43.9 ; 30.6,94.81 30.6,109.81 ; 30.607,85.5 30.607,94.8 ; 41.885,55.872 41.885,61.385 ; 41.9,26.5 41.915,31.928 ; 57.62,44.2 62.7,44.2 ; 64.599,37.1 83.3,37.1 83.3,39.4 ; 64.676,37.107 69.756,37.107 69.756,32.027 ; 69.756,56.157 69.756,61.237 ; 83.3,53.9 83.3,56.2 ; 96.943,46.759 102.023,46.759 ; 136.5,126.88 136.7,61.849 ; 152.372,126.801 152.372,121.793 157.372,121.793 ; 152.4,61.849 152.4,66.849 157.4,66.849 ; 153.3,79.8 153.3,94.8 153.3,109.7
